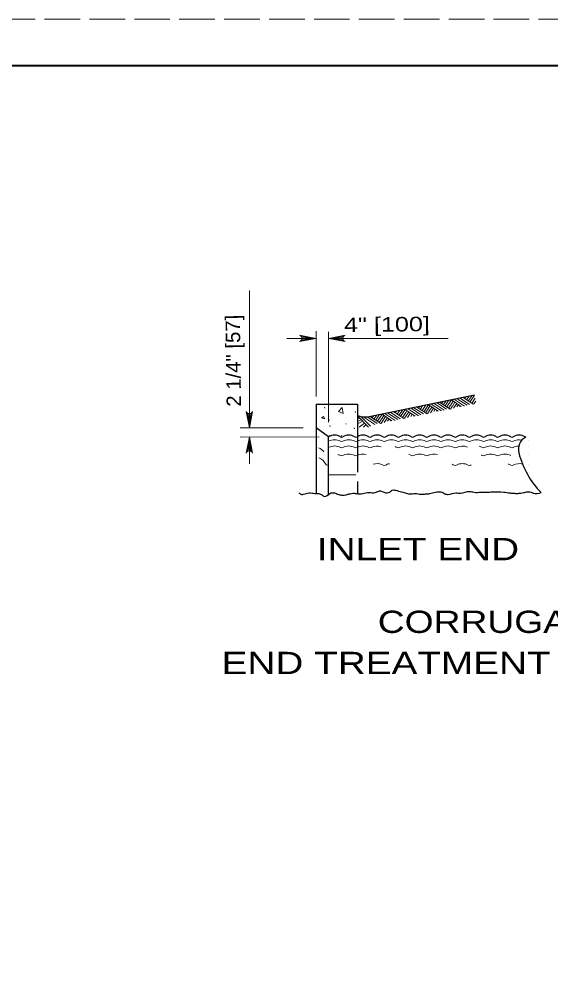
# Model space of a CAD drawing. Extents: x 1083.1 to 1117.1, y 697.4 to 743.4.
# Drawn here: x 1093.72 to 1099.45, y 709.08 to 719.35 of the extents above; entities that cross this region are included whole.
import ezdxf

# ---------------------------------------------------------------- set-up
doc = ezdxf.new("R2010")
doc.units = 0
doc.header["$LTSCALE"] = 0.064
doc.linetypes.add('LONG_DASHED', pattern=[7.5, 6, -1.5])
doc.layers.add('1', color=7, linetype='Continuous', lineweight=13)

msp = doc.modelspace()

# ---------------------------------------------------------------- linework, layer by layer
at = {"layer": '1'}
for p, q in [((1096.20158, 714.94725), (1096.20158, 716.42875)), ((1096.60417, 715.91183), (1096.92033, 715.91183)), ((1096.75817, 715.88708), (1096.92033, 715.91183)), ((1096.76008, 715.93425), (1096.92033, 715.91183)), ((1096.76433, 715.89742), (1096.92033, 715.91183)), ((1096.7655, 715.92317), (1096.92033, 715.91183)), ((1096.76717, 715.91183), (1096.92033, 715.91183)), ((1096.92033, 715.28467), (1096.92033, 715.99008)), ((1097.056, 715.00917), (1097.056, 715.98333)), ((1097.21625, 715.93425), (1097.056, 715.91183)), ((1097.21083, 715.92317), (1097.056, 715.91183)), ((1097.20917, 715.91183), (1097.056, 715.91183)), ((1097.212, 715.89742), (1097.056, 715.91183)), ((1097.21808, 715.88708), (1097.056, 715.91183)), ((1097.056, 715.91183), (1098.34475, 715.91183)), ((1098.54217, 715.24875), (1098.56692, 715.28633)), ((1098.561, 715.23642), (1098.598, 715.29275)), ((1098.57967, 715.22408), (1098.62908, 715.29908)), ((1098.04383, 715.14575), (1098.0685, 715.18333)), ((1098.06267, 715.13333), (1098.09975, 715.18975)), ((1098.08142, 715.12108), (1098.13092, 715.19625)), ((1098.13083, 715.19617), (1098.237, 715.12633)), ((1098.13725, 715.16508), (1098.14958, 715.18383)), ((1098.162, 715.20258), (1098.273, 715.12967)), ((1098.19317, 715.20908), (1098.30042, 715.1385)), ((1098.22417, 715.2155), (1098.3265, 715.14825)), ((1098.25542, 715.22192), (1098.36592, 715.14933)), ((1098.27417, 715.20958), (1098.28658, 715.22842)), ((1098.29292, 715.19725), (1098.31775, 715.23483)), ((1098.31175, 715.18492), (1098.34892, 715.24125)), ((1098.3305, 715.17242), (1098.38008, 715.24767)), ((1098.34933, 715.16017), (1098.386, 715.21583)), ((1098.36917, 715.14933), (1098.39233, 715.18458)), ((1098.38, 715.24775), (1098.48617, 715.17783)), ((1098.38633, 715.21658), (1098.39867, 715.23542)), ((1098.39292, 715.18533), (1098.4175, 715.223)), ((1098.40358, 715.16083), (1098.43633, 715.21067)), ((1098.411, 715.25417), (1098.52208, 715.18117)), ((1098.43883, 715.1735), (1098.45508, 715.19833)), ((1098.44217, 715.26058), (1098.54942, 715.19008)), ((1098.46808, 715.177), (1098.47392, 715.18592)), ((1098.47333, 715.267), (1098.57558, 715.19983)), ((1098.50458, 715.2735), (1098.61492, 715.20083)), ((1098.52333, 715.26117), (1098.53567, 715.27983)), ((1098.5985, 715.21167), (1098.635, 715.26733)), ((1098.61833, 715.20083), (1098.6415, 715.23608)), ((1096.17917, 715.1075), (1096.20158, 714.94725)), ((1096.19025, 715.10208), (1096.20158, 714.94725)), ((1096.22633, 715.10933), (1096.20158, 714.94725)), ((1096.216, 715.10325), (1096.20158, 714.94725)), ((1096.20158, 715.10042), (1096.20158, 714.94725)), ((1097.01608, 715.15917), (1097.01167, 715.16917)), ((1097.34725, 715.11367), (1097.34275, 715.12367)), ((1097.54567, 715.04275), (1097.57025, 715.08042)), ((1097.56442, 715.03042), (1097.6015, 715.08683)), ((1097.58317, 715.01808), (1097.63267, 715.09317)), ((1097.6325, 715.09317), (1097.73883, 715.02325)), ((1097.63908, 715.06208), (1097.65133, 715.08092)), ((1097.66375, 715.09967), (1097.77475, 715.02667)), ((1097.69483, 715.10617), (1097.80208, 715.0355)), ((1097.726, 715.11258), (1097.82825, 715.04533)), ((1097.75708, 715.119), (1097.86758, 715.04642)), ((1097.77592, 715.10658), (1097.78833, 715.12542)), ((1097.79475, 715.09425), (1097.8195, 715.13192)), ((1097.8135, 715.08183), (1097.85058, 715.13825)), ((1097.83233, 715.0695), (1097.88175, 715.14475)), ((1097.85117, 715.05717), (1097.88758, 715.11292)), ((1097.87092, 715.04642), (1097.89408, 715.08167)), ((1097.88167, 715.14475), (1097.988, 715.07475)), ((1097.888, 715.11367), (1097.9005, 715.13242)), ((1097.89458, 715.08242), (1097.91925, 715.12008)), ((1097.90525, 715.05792), (1097.93808, 715.10767)), ((1097.91283, 715.15117), (1098.02392, 715.07817)), ((1097.94058, 715.07058), (1097.95692, 715.09533)), ((1097.94392, 715.15758), (1098.05125, 715.087)), ((1097.96992, 715.07417), (1097.97567, 715.083)), ((1097.97517, 715.164), (1098.07733, 715.09692)), ((1098.00633, 715.1705), (1098.11667, 715.09792)), ((1098.025, 715.15808), (1098.03742, 715.17692)), ((1098.10025, 715.10875), (1098.13683, 715.16433)), ((1098.12008, 715.09792), (1098.14317, 715.13317)), ((1098.14375, 715.13392), (1098.1685, 715.1715)), ((1098.1545, 715.10942), (1098.18717, 715.15917)), ((1098.18967, 715.12208), (1098.206, 715.14675)), ((1098.21892, 715.12567), (1098.22475, 715.13442)), ((1097.06483, 715.03492), (1097.06033, 715.02825)), ((1097.24625, 714.985), (1097.24183, 714.995)), ((1097.36583, 715.04008), (1097.39117, 715.052)), ((1097.36583, 714.99033), (1097.42442, 715.01783)), ((1097.36592, 715.078), (1097.48533, 714.95533)), ((1097.36592, 715.01517), (1097.40775, 715.03483)), ((1097.38467, 714.95533), (1097.44417, 714.9975)), ((1097.41175, 715.06317), (1097.50592, 714.96633)), ((1097.43325, 714.95533), (1097.45992, 714.98142)), ((1097.43567, 715.06117), (1097.55292, 714.98417)), ((1097.47683, 715.06108), (1097.57908, 714.99383)), ((1097.50808, 715.06742), (1097.61842, 714.995)), ((1097.52683, 715.05517), (1097.53917, 715.07383)), ((1097.602, 715.00575), (1097.63858, 715.06125)), ((1097.62183, 714.99483), (1097.645, 715.03017)), ((1097.6455, 715.03092), (1097.67017, 715.0685)), ((1097.65617, 715.00633), (1097.68892, 715.05608)), ((1097.69133, 715.01908), (1097.70775, 715.04383)), ((1097.72067, 715.02267), (1097.7265, 715.03142)), ((1096.78175, 714.94725), (1096.10133, 714.94767)), ((1097.07317, 714.96183), (1097.06875, 714.97183)), ((1097.33608, 714.93633), (1097.33167, 714.94633)), ((1096.95367, 714.85092), (1096.10133, 714.84792)), ((1096.17675, 714.68892), (1096.20158, 714.851)), ((1096.18717, 714.695), (1096.20158, 714.851)), ((1096.20158, 714.85125), (1096.20158, 714.5575)), ((1096.20158, 714.69783), (1096.20158, 714.851)), ((1096.21292, 714.69617), (1096.20158, 714.851)), ((1096.224, 714.69075), (1096.20158, 714.851)), ((1097.19742, 714.86525), (1097.193, 714.85858)), ((1097.056, 714.44033), (1097.34967, 714.44033))]:
    msp.add_line(p, q, dxfattribs=at)
at = {"layer": '1', "lineweight": 25}
for p, q in [((1096.92033, 715.20383), (1096.92025, 714.24083)), ((1096.92033, 715.20383), (1097.36592, 715.20383)), ((1097.36592, 715.20383), (1097.36583, 714.85325))]:
    msp.add_line(p, q, dxfattribs=at)
at = {"layer": '1', "linetype": 'LONG_DASHED', "lineweight": 25}
msp.add_line((1097.36583, 714.85325), (1097.36592, 714.23767), dxfattribs=at)
at = {"layer": '1', "linetype": 'LONG_DASHED'}
msp.add_lwpolyline([(1083.12642, 697.35408), (1117.12642, 697.35408), (1117.12642, 719.35408), (1083.12642, 719.35408)], close=True, dxfattribs=at)
at = {"layer": '1', "lineweight": 25}
msp.add_lwpolyline([(1085.12642, 718.85408), (1116.62642, 718.85408), (1116.62642, 697.85408), (1085.12642, 697.85408)], close=True, dxfattribs=at)
at = {"layer": '1', "lineweight": 40}
msp.add_lwpolyline([(1085.12642, 718.85408), (1116.62642, 718.85408), (1116.62642, 697.85408), (1085.12642, 697.85408)], close=True, dxfattribs=at)
msp.add_lwpolyline([(1085.12642, 718.85408), (1116.62642, 718.85408), (1116.62642, 697.85408), (1085.12642, 697.85408)], close=True, dxfattribs=at)
at = {"layer": '1'}
for points in [[(1096.74333, 715.87642), (1096.92033, 715.91183), (1096.74333, 715.94725)], [(1097.233, 715.87642), (1097.056, 715.91183), (1097.233, 715.94725)], [(1096.237, 715.12425), (1096.20158, 714.94725), (1096.16617, 715.12425)], [(1097.21225, 715.10225), (1097.20342, 715.16558), (1097.16367, 715.12458), (1097.21125, 715.10258)], [(1096.16617, 714.674), (1096.20158, 714.851), (1096.237, 714.674)], [(1097.07175, 714.85567), (1097.06767, 714.86417), (1097.05025, 714.85125)]]:
    msp.add_lwpolyline(points, dxfattribs=at)
at = {"layer": '1', "lineweight": 25}
for points in [[(1098.62908, 715.299), (1097.47492, 715.06067), (1097.41633, 715.06142), (1097.38358, 715.07325), (1097.36592, 715.07958)], [(1097.056, 714.23342), (1097.056, 714.85125), (1096.92033, 714.94717)]]:
    msp.add_lwpolyline(points, dxfattribs=at)
at = {"layer": '1'}
msp.add_lwpolyline([(1097.01392, 715.04267), (1097.00058, 715.07042), (1096.97842, 715.05375)], close=True, dxfattribs=at)
for centre, start, end in [((1096.72903, 715.91188), 292.08605, 67.91218), ((1097.24727, 715.91188), 112.08782, 247.91395), ((1096.20154, 715.13853), 202.08782, 337.91395), ((1096.2016, 714.65972), 22.08782, 157.91395)]:
    msp.add_arc(centre, 0.0382, start, end, dxfattribs=at)
at = {"layer": '1', "lineweight": 25}
for centre, major_axis, start_param, end_param in [((1097.11986, 714.73792), (-0.13004, 0), 4.19883845, 5.22593946), ((1097.19637, 714.87162), (-0.02402, 0), 1.01768059, 2.12391206), ((1097.27288, 714.73792), (-0.13004, 0), 4.19883845, 5.22593946), ((1097.34938, 714.87162), (-0.02402, 0), 1.01768059, 2.12391206), ((1097.42589, 714.73792), (-0.13004, 0), 4.19883845, 5.22593946), ((1097.50239, 714.87162), (-0.02402, 0), 1.01768059, 2.12391206), ((1097.5789, 714.73792), (-0.13004, 0), 4.19883845, 5.22593946), ((1097.6554, 714.87162), (-0.02402, 0), 1.01768059, 2.12391206), ((1097.73191, 714.73792), (-0.13004, 0), 4.19883845, 5.22593946), ((1097.80841, 714.87162), (-0.02402, 0), 1.01768059, 2.12391206), ((1097.88492, 714.73792), (-0.13004, 0), 4.19883845, 5.22593946), ((1097.96143, 714.87162), (-0.02402, 0), 1.01768059, 2.12391206), ((1098.03793, 714.73792), (-0.13004, 0), 4.19883845, 5.22593946), ((1098.11444, 714.87162), (-0.02402, 0), 1.01768059, 2.12391206), ((1098.19094, 714.73792), (-0.13004, 0), 4.19883845, 5.22593946), ((1098.26745, 714.87162), (-0.02402, 0), 1.01768059, 2.12391206), ((1098.34395, 714.73792), (-0.13004, 0), 4.19883845, 5.22593946), ((1098.42046, 714.87162), (-0.02402, 0), 1.01768059, 2.12391206), ((1098.49697, 714.73792), (-0.13004, 0), 4.19883845, 5.22593946), ((1098.57347, 714.87162), (-0.02402, 0), 1.01768059, 2.12391206), ((1098.64998, 714.73792), (-0.13004, 0), 4.19883845, 5.22593946), ((1098.72648, 714.87162), (-0.02402, 0), 1.01768059, 2.12391206), ((1098.80299, 714.73792), (-0.13004, 0), 4.19883845, 5.22593946), ((1098.87949, 714.87162), (-0.02402, 0), 1.01768059, 2.12391206), ((1098.956, 714.73792), (-0.13004, 0), 4.19883845, 5.22593946), ((1099.03251, 714.87162), (-0.02402, 0), 1.01768059, 2.12391206), ((1099.10901, 714.73792), (-0.13004, 0), 4.19883845, 5.22593946), ((1099.25039, 714.71633), (-0.14894, 0), 5.20408789, 6.5554381), ((1099.18552, 714.87162), (-0.02402, 0), 1.01768059, 1.3474574), ((1100.01407, 714.90273), (-0.93499, 0), 0.24461371, 0.77495004)]:
    msp.add_ellipse(centre, major_axis=major_axis, ratio=0.999895, start_param=start_param, end_param=end_param, dxfattribs=at)
at = {"layer": '1'}
for centre, major_axis, start_param, end_param in [((1097.11986, 714.68912), (-0.13004, 0), 4.19883845, 5.22593946), ((1097.19637, 714.82281), (-0.02402, 0), 1.01768059, 2.12391206), ((1097.27288, 714.68912), (-0.13004, 0), 4.19883845, 5.22593946), ((1097.34938, 714.82281), (-0.02402, 0), 1.01768059, 2.12391206), ((1097.42589, 714.68912), (-0.13004, 0), 4.19883845, 5.22593946), ((1097.50239, 714.82281), (-0.02402, 0), 1.01768059, 2.12391206), ((1097.5789, 714.68912), (-0.13004, 0), 4.19883845, 5.22593946), ((1097.6554, 714.82281), (-0.02402, 0), 1.01768059, 2.12391206), ((1097.73191, 714.68912), (-0.13004, 0), 4.19883845, 5.22593946), ((1097.80841, 714.82281), (-0.02402, 0), 1.01768059, 2.12391206), ((1097.88492, 714.68912), (-0.13004, 0), 4.19883845, 5.22593946), ((1097.96143, 714.82281), (-0.02402, 0), 1.01768059, 2.12391206), ((1098.03793, 714.68912), (-0.13004, 0), 4.19883845, 5.22593946), ((1098.11444, 714.82281), (-0.02402, 0), 1.01768059, 2.12391206), ((1098.19094, 714.68912), (-0.13004, 0), 4.19883845, 5.22593946), ((1098.26745, 714.82281), (-0.02402, 0), 1.01768059, 2.12391206), ((1098.34395, 714.68912), (-0.13004, 0), 4.19883845, 5.22593946), ((1098.42046, 714.82281), (-0.02402, 0), 1.01768059, 2.12391206), ((1098.49697, 714.68912), (-0.13004, 0), 4.19883845, 5.22593946), ((1098.57347, 714.82281), (-0.02402, 0), 1.01768059, 2.12391206), ((1098.64998, 714.68912), (-0.13004, 0), 4.19883845, 5.22593946), ((1098.72648, 714.82281), (-0.02402, 0), 1.01768059, 2.12391206), ((1098.80299, 714.68912), (-0.13004, 0), 4.19883845, 5.22593946), ((1098.87949, 714.82281), (-0.02402, 0), 1.01768059, 2.12391206), ((1098.956, 714.68912), (-0.13004, 0), 4.19883845, 5.22593946), ((1099.03251, 714.82281), (-0.02402, 0), 1.01768059, 2.12391206), ((1099.10901, 714.68912), (-0.13004, 0), 4.49056961, 5.22593946), ((1099.26202, 714.68912), (-0.13004, 0), 5.0948343, 5.09495041), ((1096.901, 714.60981), (0.13004, 0), 0.64326107, 1.197681), ((1097.11986, 714.62141), (-0.13004, 0), 4.19883845, 5.22593946), ((1097.19637, 714.7551), (-0.02402, 0), 1.01768059, 2.12391206), ((1097.27288, 714.62141), (-0.13004, 0), 4.19883845, 5.22593946), ((1097.27288, 714.53471), (-0.13004, 0), 4.19883845, 5.22593946), ((1097.34938, 714.7551), (-0.02402, 0), 1.01768059, 2.12391206), ((1097.42589, 714.62141), (-0.13004, 0), 4.19883845, 5.22593946), ((1097.42589, 714.53471), (-0.13004, 0), 4.42922977, 5.22593946), ((1097.50239, 714.7551), (-0.02402, 0), 1.01768059, 2.12391206), ((1097.5789, 714.62141), (-0.13004, 0), 4.37296685, 5.22593946), ((1097.73191, 714.62141), (-0.13004, 0), 4.19883845, 4.37726652), ((1097.80841, 714.7551), (-0.02402, 0), 1.01768059, 2.12391206), ((1097.88492, 714.62141), (-0.13004, 0), 4.19883845, 5.22593946), ((1097.96143, 714.7551), (-0.02402, 0), 1.01768059, 2.12391206), ((1098.03793, 714.62141), (-0.13004, 0), 4.19883845, 5.22593946), ((1098.03793, 714.53471), (-0.13004, 0), 4.19883845, 5.22593946), ((1098.11444, 714.7551), (-0.02402, 0), 1.01768059, 2.12391206), ((1098.19094, 714.62141), (-0.13004, 0), 4.19883845, 5.22593946), ((1098.19094, 714.53471), (-0.13004, 0), 4.40332297, 5.22593946), ((1098.26745, 714.7551), (-0.02402, 0), 1.01768059, 2.12391206), ((1098.34395, 714.62141), (-0.13004, 0), 4.19883845, 5.22593946), ((1098.42046, 714.7551), (-0.02402, 0), 1.01768059, 2.12391206), ((1098.49697, 714.62141), (-0.13004, 0), 4.27344086, 5.22593946), ((1098.64998, 714.62141), (-0.13004, 0), 4.19883845, 4.47847317), ((1098.72648, 714.7551), (-0.02402, 0), 1.01768059, 2.12391206), ((1098.80299, 714.62141), (-0.13004, 0), 4.19883845, 5.22593946), ((1098.80299, 714.53471), (-0.13004, 0), 4.19883845, 5.22593946), ((1098.87949, 714.7551), (-0.02402, 0), 1.01768059, 2.12391206), ((1098.956, 714.62141), (-0.13004, 0), 4.19883845, 5.22593946), ((1098.956, 714.53471), (-0.13004, 0), 4.20364688, 5.22593946), ((1099.03251, 714.7551), (-0.02402, 0), 1.01768059, 2.12391206), ((1099.10901, 714.62141), (-0.13004, 0), 4.75778771, 5.22593946), ((1099.26202, 714.62141), (-0.13004, 0), 5.0948343, 5.09495041), ((1096.90413, 714.50312), (0.13004, 0), 0.44130689, 1.197681), ((1097.11986, 714.53471), (-0.13004, 0), 4.19883845, 4.43555484), ((1097.19637, 714.6684), (-0.02402, 0), 1.01768059, 2.12391206), ((1097.34938, 714.6684), (-0.02402, 0), 1.01768059, 2.12391206), ((1097.5789, 714.43177), (-0.13004, 0), 4.19883845, 5.04999015), ((1097.88492, 714.53471), (-0.13004, 0), 4.19883845, 4.42398108), ((1097.96143, 714.6684), (-0.02402, 0), 1.01768059, 2.12391206), ((1098.11444, 714.6684), (-0.02402, 0), 1.01768059, 2.12391206), ((1098.49697, 714.43177), (-0.13004, 0), 4.19883845, 5.22593946), ((1098.64998, 714.53471), (-0.13004, 0), 4.19883845, 4.30381535), ((1098.72648, 714.6684), (-0.02402, 0), 1.01768059, 2.12391206), ((1098.87949, 714.6684), (-0.02402, 0), 1.01768059, 2.12391206), ((1099.10901, 714.43177), (-0.13004, 0), 4.43004663, 5.22593946), ((1099.26202, 714.53471), (-0.13004, 0), 5.0948343, 5.09495041), ((1097.04382, 714.56805), (-0.02402, 0), 0.40174168, 1.50797315), ((1097.02902, 714.41473), (0.13004, 0), 1.33730274, 1.4684079), ((1097.6554, 714.56546), (-0.02402, 0), 1.01768059, 2.12391206), ((1097.73191, 714.43177), (-0.13004, 0), 4.87822498, 5.22593946), ((1098.34395, 714.43177), (-0.13004, 0), 4.19883845, 4.36348263), ((1098.42046, 714.56546), (-0.02402, 0), 1.01768059, 2.12391206), ((1098.57347, 714.56546), (-0.02402, 0), 1.01768059, 2.12391206), ((1098.64998, 714.43177), (-0.13004, 0), 5.1867846, 5.22593946), ((1098.956, 714.43177), (-0.13004, 0), 4.19883845, 4.44072538), ((1099.03251, 714.56546), (-0.02402, 0), 1.01768059, 2.12391206), ((1099.26202, 714.43177), (-0.13004, 0), 5.0948343, 5.09495041)]:
    msp.add_ellipse(centre, major_axis=major_axis, ratio=0.999895, start_param=start_param, end_param=end_param, dxfattribs=at)
at = {"layer": '1', "lineweight": 25}
for points in [[(1096.73333, 714.24783), (1096.76308, 714.22917), (1096.78292, 714.23158), (1096.84533, 714.24608), (1096.87717, 714.24392), (1096.93925, 714.23942), (1096.96192, 714.23717), (1097.01258, 714.20675), (1097.0695, 714.24017), (1097.11817, 714.24517), (1097.16467, 714.22892), (1097.18267, 714.22425), (1097.23725, 714.22458), (1097.2755, 714.23417), (1097.33167, 714.2415), (1097.35292, 714.23925), (1097.39067, 714.23475), (1097.45758, 714.24692), (1097.49267, 714.2495), (1097.55767, 714.24983), (1097.596, 714.26425), (1097.61567, 714.26667), (1097.65333, 714.25267), (1097.717, 714.25542), (1097.74175, 714.27433), (1097.79458, 714.27), (1097.85642, 714.25367), (1097.9045, 714.23983), (1097.92708, 714.23517), (1097.98942, 714.24025), (1098.04975, 714.23108), (1098.08775, 714.23367), (1098.13483, 714.23625), (1098.18825, 714.25075), (1098.26708, 714.25592), (1098.28525, 714.25133), (1098.30758, 714.23717), (1098.34533, 714.23025), (1098.426, 714.24492), (1098.479, 714.24292), (1098.57642, 714.26225), (1098.62317, 714.25308), (1098.699, 714.2535), (1098.75658, 714.25367), (1098.82025, 714.2565), (1098.943, 714.25467), (1099.0095, 714.24558), (1099.05775, 714.24117), (1099.10633, 714.24133), (1099.12908, 714.24392), (1099.155, 714.24875)], [(1099.155, 714.24875), (1099.19992, 714.25767), (1099.2245, 714.25642), (1099.253, 714.24733), (1099.26075, 714.24333), (1099.34608, 714.24867)]]:
    msp.add_spline(points, degree=3, dxfattribs=at)

# ---------------------------------------------------------------- texts
at = {"layer": '1'}
for s, rotation, width, p in [('2 1/4" [57]', 90.75, 1.05, (1096.11267, 715.17658)), ('4" [100]', 0.75, 1.3, (1097.22275, 715.97825))]:
    msp.add_text(s, height=0.156, rotation=rotation, dxfattribs=dict(at, width=width)).set_placement(p)
for s, width, p in [('INLET END', 1.3, (1096.92967, 713.51975)), ('CORRUGATED PIPE', 1.25, (1097.58583, 712.73608)), ('END TREATMENT OF HEADWALL', 1.3, (1095.90267, 712.2925))]:
    msp.add_text(s, height=0.24, dxfattribs=dict(at, width=width)).set_placement(p)

doc.saveas('drawing.dxf')
